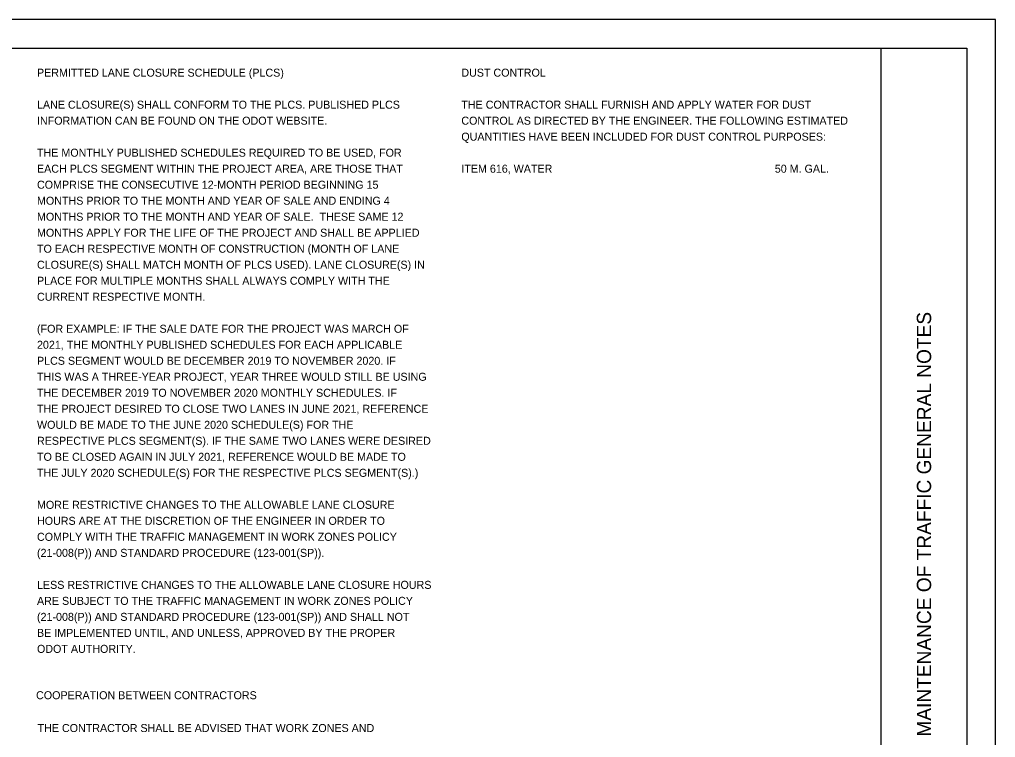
# Model space of a CAD drawing. Extents: x 0 to 34, y 0 to 22.
# Drawn here: x 16.93 to 34, y 9.44 to 22 of the extents above; entities that cross this region are included whole.
import ezdxf

# ---------------------------------------------------------------- set-up
doc = ezdxf.new("R2010")
doc.units = 0
for name, color, linetype in [('SH_Border', 7, 'Continuous'), ('SH_Cut_Line', 7, 'Continuous'), ('SH_Data', 7, 'Continuous'), ('SH_Text', 7, 'Continuous')]:
    doc.layers.add(name, color=color, linetype=linetype)

msp = doc.modelspace()

# ---------------------------------------------------------------- linework, layer by layer
at = {"layer": 'SH_Border'}
msp.add_line((32, 0.5), (32, 21.5), dxfattribs=at)
msp.add_lwpolyline([(1.5, 21.5), (33.5, 21.5), (33.5, 0.5), (1.5, 0.5)], close=True, dxfattribs=at)
at = {"layer": 'SH_Cut_Line'}
msp.add_lwpolyline([(0, 0), (34, 0), (34, 22), (0, 22)], close=True, dxfattribs=at)

# ---------------------------------------------------------------- texts
at = {"layer": 'SH_Data'}
msp.add_text('MAINTENANCE OF TRAFFIC GENERAL NOTES', height=0.25, rotation=90, dxfattribs=at).set_placement((32.875, 9.455))
at = {"layer": 'SH_Text'}
for s, p in [('PERMITTED LANE CLOSURE SCHEDULE (PLCS)', (17.24, 21)), ('DUST CONTROL', (24.66, 21)), ('LANE CLOSURE(S) SHALL CONFORM TO THE PLCS. PUBLISHED PLCS ', (17.24, 20.44)), ('THE CONTRACTOR SHALL FURNISH AND APPLY WATER FOR DUST ', (24.66, 20.44)), ('INFORMATION CAN BE FOUND ON THE ODOT WEBSITE.', (17.24, 20.16)), ('CONTROL AS DIRECTED BY THE ENGINEER. THE FOLLOWING ESTIMATED ', (24.66, 20.16)), ('QUANTITIES HAVE BEEN INCLUDED FOR DUST CONTROL PURPOSES:', (24.66, 19.88)), ('THE MONTHLY PUBLISHED SCHEDULES REQUIRED TO BE USED, FOR ', (17.24, 19.6)), ('EACH PLCS SEGMENT WITHIN THE PROJECT AREA, ARE THOSE THAT ', (17.24, 19.32)), ('ITEM 616, WATER', (24.66, 19.32)), ('50 M. GAL.', (30.141, 19.32)), ('COMPRISE THE CONSECUTIVE 12-MONTH PERIOD BEGINNING 15 ', (17.24, 19.04)), ('MONTHS PRIOR TO THE MONTH AND YEAR OF SALE AND ENDING 4 ', (17.24, 18.76)), ('MONTHS PRIOR TO THE MONTH AND YEAR OF SALE.  THESE SAME 12 ', (17.24, 18.48)), ('MONTHS APPLY FOR THE LIFE OF THE PROJECT AND SHALL BE APPLIED ', (17.24, 18.2)), ('TO EACH RESPECTIVE MONTH OF CONSTRUCTION (MONTH OF LANE ', (17.24, 17.92)), ('CLOSURE(S) SHALL MATCH MONTH OF PLCS USED). LANE CLOSURE(S) IN ', (17.24, 17.64)), ('PLACE FOR MULTIPLE MONTHS SHALL ALWAYS COMPLY WITH THE ', (17.24, 17.36)), ('CURRENT RESPECTIVE MONTH. ', (17.24, 17.08)), ('(FOR EXAMPLE: IF THE SALE DATE FOR THE PROJECT WAS MARCH OF ', (17.24, 16.52)), ('2021, THE MONTHLY PUBLISHED SCHEDULES FOR EACH APPLICABLE ', (17.24, 16.24)), ('PLCS SEGMENT WOULD BE DECEMBER 2019 TO NOVEMBER 2020. IF ', (17.24, 15.96)), ('THIS WAS A THREE-YEAR PROJECT, YEAR THREE WOULD STILL BE USING ', (17.24, 15.68)), ('THE DECEMBER 2019 TO NOVEMBER 2020 MONTHLY SCHEDULES. IF ', (17.24, 15.4)), ('THE PROJECT DESIRED TO CLOSE TWO LANES IN JUNE 2021, REFERENCE ', (17.24, 15.12)), ('WOULD BE MADE TO THE JUNE 2020 SCHEDULE(S) FOR THE ', (17.24, 14.84)), ('RESPECTIVE PLCS SEGMENT(S). IF THE SAME TWO LANES WERE DESIRED ', (17.24, 14.56)), ('TO BE CLOSED AGAIN IN JULY 2021, REFERENCE WOULD BE MADE TO ', (17.24, 14.28)), ('THE JULY 2020 SCHEDULE(S) FOR THE RESPECTIVE PLCS SEGMENT(S).)', (17.24, 14)), ('MORE RESTRICTIVE CHANGES TO THE ALLOWABLE LANE CLOSURE ', (17.24, 13.44)), ('HOURS ARE AT THE DISCRETION OF THE ENGINEER IN ORDER TO ', (17.24, 13.16)), ('COMPLY WITH THE TRAFFIC MANAGEMENT IN WORK ZONES POLICY ', (17.24, 12.88)), ('(21-008(P)) AND STANDARD PROCEDURE (123-001(SP)). ', (17.24, 12.6)), ('LESS RESTRICTIVE CHANGES TO THE ALLOWABLE LANE CLOSURE HOURS ', (17.24, 12.04)), ('ARE SUBJECT TO THE TRAFFIC MANAGEMENT IN WORK ZONES POLICY ', (17.24, 11.76)), ('(21-008(P)) AND STANDARD PROCEDURE (123-001(SP)) AND SHALL NOT ', (17.24, 11.48)), ('BE IMPLEMENTED UNTIL, AND UNLESS, APPROVED BY THE PROPER ', (17.24, 11.2)), ('ODOT AUTHORITY.', (17.24, 10.92)), ('COOPERATION BETWEEN CONTRACTORS', (17.224, 10.109)), ('THE CONTRACTOR SHALL BE ADVISED THAT WORK ZONES AND', (17.25, 9.535))]:
    msp.add_text(s, height=0.14, dxfattribs=at).set_placement(p)

doc.saveas('drawing.dxf')
